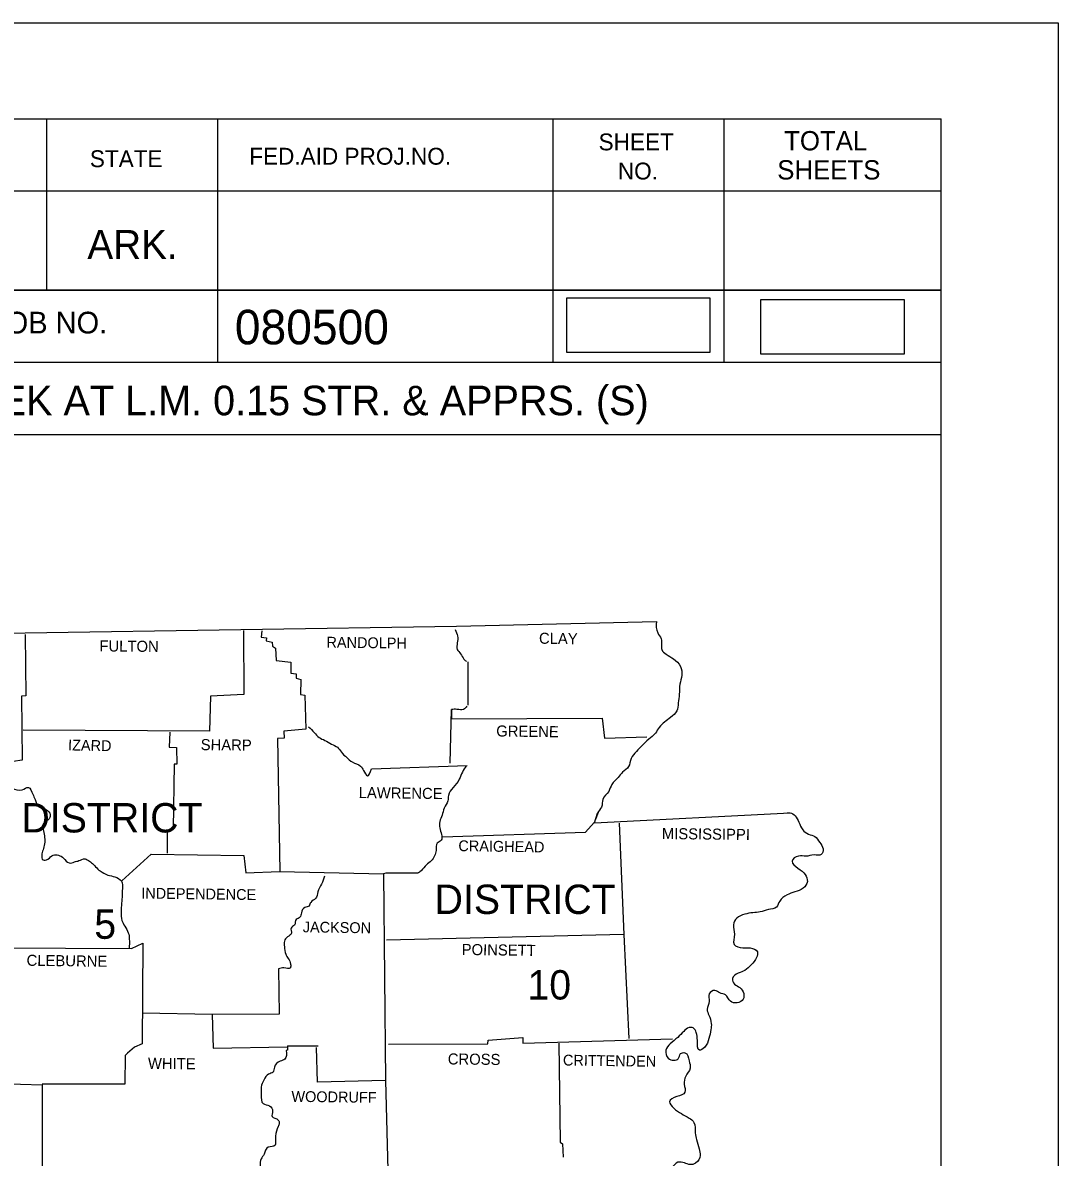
# Model space of a CAD drawing. Extents: x 1374139 to 1377472, y 1168351 to 1170484.
# Drawn here: x 1377052.4 to 1377472.1, y 1170024.3 to 1170484.1 of the extents above; entities that cross this region are included whole.
import ezdxf

# ---------------------------------------------------------------- set-up
doc = ezdxf.new("R2010")
doc.units = 0
for name, color, linetype in [('15', 7, 'Continuous'), ('26', 7, 'Continuous'), ('6', 7, 'Continuous'), ('Default', 7, 'Continuous')]:
    doc.layers.add(name, color=color, linetype=linetype)

msp = doc.modelspace()

# ---------------------------------------------------------------- linework, layer by layer
at = {"layer": '15'}
for points in [[(1377272.75, 1170350.59), (1377331.08, 1170350.59), (1377331.08, 1170372.46), (1377272.75, 1170372.46)], [(1377351.45, 1170349.9), (1377409.78, 1170349.9), (1377409.78, 1170371.76), (1377351.45, 1170371.76)]]:
    msp.add_lwpolyline(points, close=True, dxfattribs=at)
at = {"layer": '26'}
msp.add_line((1374138.81, 1170484.1), (1377472.14, 1170484.1), dxfattribs=at)
msp.add_lwpolyline([(1374138.74, 1170484.1), (1377472.14, 1170484.1), (1377472.14, 1168350.73), (1374138.74, 1168350.73)], close=True, dxfattribs=at)
at = {"layer": '6'}
for p, q in [((1374262.81, 1170445.16), (1377424.61, 1170445.16)), ((1377062.01, 1170445.16), (1377062.01, 1170375.76)), ((1377131.41, 1170445.16), (1377131.41, 1170346.36)), ((1377267.21, 1170445.16), (1377267.21, 1170346.36)), ((1377336.61, 1170445.16), (1377336.61, 1170346.36)), ((1377424.61, 1168390.56), (1377424.61, 1170445.16)), ((1377424.61, 1170415.76), (1376993.61, 1170415.76)), ((1377424.61, 1170415.96), (1377424.61, 1170415.96)), ((1377424.61, 1170375.76), (1376993.61, 1170375.76)), ((1377023.21, 1170375.76), (1377424.61, 1170375.76)), ((1377424.61, 1170346.36), (1376602.01, 1170346.36)), ((1376993.61, 1170317.16), (1377424.61, 1170317.16))]:
    msp.add_line(p, q, dxfattribs=at)
at = {"layer": 'Default'}
for p, q in [((1377284.18, 1170159.85), (1377285.43, 1170163.71)), ((1377284.49, 1170161.1), (1377285.75, 1170164.13)), ((1377159.72, 1170069.43), (1377172.15, 1170069.43))]:
    msp.add_line(p, q, dxfattribs=at)
for points in [[(1376736.44, 1170236.59), (1376905.27, 1170236.48), (1377053.43, 1170236.8), (1377228.22, 1170239.51), (1377309.24, 1170241.39)], [(1377053.43, 1170236.17), (1377053.64, 1170211.32), (1377051.86, 1170211.22), (1377052.18, 1170185.22), (1377044.87, 1170184.18), (1377045.49, 1170177.18), (1377048, 1170173.94), (1377047.79, 1170165.7), (1377033.59, 1170165.17), (1377033.07, 1170152.44), (1377020.12, 1170152.02), (1377019.5, 1170136.57), (1377020.23, 1170135.31), (1377020.54, 1170110.67), (1377042.88, 1170109.21), (1377042.57, 1170054.19), (1377060.32, 1170053.66), (1377060.32, 1169997.7), (1377046.33, 1169996.66), (1377045.29, 1169984.34), (1377021.79, 1169984.23)], [(1377141.87, 1170237.74), (1377142.08, 1170211.84), (1377128.5, 1170211.11), (1377128.08, 1170196.91), (1377052.59, 1170197.33)], [(1377149.38, 1170237.63), (1377149.07, 1170235.13), (1377151.16, 1170234.81), (1377151.06, 1170233.56), (1377153.46, 1170233.04), (1377153.67, 1170231.37), (1377154.81, 1170230.64), (1377155.13, 1170225.63), (1377161.08, 1170225), (1377161.08, 1170220.51), (1377163.27, 1170220.2), (1377163.27, 1170218.42), (1377165.15, 1170217.9), (1377165.05, 1170211.84), (1377166.72, 1170211.53), (1377167.13, 1170197.85), (1377158.26, 1170197.02), (1377158.36, 1170194.09), (1377155.65, 1170193.99), (1377156.59, 1170140.12), (1377198.67, 1170139.18), (1377199.4, 1170055.44), (1377171.94, 1170054.71), (1377171.42, 1170068.8)], [(1377232.81, 1170225.1), (1377232.81, 1170207.46)], [(1377225.71, 1170183.97), (1377226.23, 1170205.79), (1377226.23, 1170201.93), (1377287.31, 1170202.24), (1377288.15, 1170194.09), (1377305.38, 1170194.72)], [(1377112.01, 1170196.6), (1377111.8, 1170190.54), (1377114.72, 1170190.34), (1377114.82, 1170183.65), (1377113.78, 1170183.65), (1377113.36, 1170157.34), (1377110.96, 1170156.3), (1377110.96, 1170147.53)], [(1377193.76, 1170181.67), (1377232.5, 1170183.03)], [(1377284.18, 1170159.85), (1377363.43, 1170163.92)], [(1377222.58, 1170154.11), (1377280.53, 1170155.99), (1377283.97, 1170159.95)], [(1377294.2, 1170159.74), (1377295.98, 1170114.53), (1377298.07, 1170072.46)], [(1377092.58, 1170136.36), (1377104.49, 1170147.11), (1377142.08, 1170146.59), (1377142.81, 1170139.59), (1377156.48, 1170140.12)], [(1377212.35, 1170139.38), (1377199.61, 1170139.38), (1377198.67, 1170139.18)], [(1377295.98, 1170114.53), (1377199.82, 1170112.34)], [(1377042.88, 1170109.21), (1377096.55, 1170108.9), (1377101.15, 1170111.09), (1377100.83, 1170070.27), (1377097.7, 1170068.91), (1377094.88, 1170066.51), (1377093.94, 1170065.57), (1377093.84, 1170053.87), (1377060.32, 1170053.87)], [(1377156.07, 1170100.65), (1377156.28, 1170082.27), (1377129.13, 1170082.17), (1377100.93, 1170082.7)], [(1377129.13, 1170082.17), (1377129.55, 1170068.49), (1377159.72, 1170069.03)], [(1377159.72, 1170069.43), (1377159.72, 1170067.66), (1377159.2, 1170067.55)], [(1377200.65, 1170070.06), (1377240.95, 1170070.27), (1377241.06, 1170071.73), (1377255.05, 1170072.77), (1377255.05, 1170070.58), (1377315.82, 1170072.25)], [(1377269.67, 1170070.58), (1377270.19, 1170030.38), (1377271.13, 1170029.75), (1377271.44, 1170024.33)], [(1377269.67, 1170070.58), (1377270.19, 1170030.38), (1377271.13, 1170029.75), (1377271.44, 1170024.33)], [(1377269.67, 1170070.58), (1377270.19, 1170030.38), (1377271.13, 1170029.75), (1377271.44, 1170024.33)], [(1377269.67, 1170070.58), (1377270.19, 1170030.38), (1377271.13, 1170029.75), (1377271.44, 1170024.33)], [(1377269.67, 1170070.58), (1377270.19, 1170030.38), (1377271.13, 1170029.75), (1377271.44, 1170024.33)], [(1377199.4, 1170055.44), (1377200.96, 1169998.22), (1377176.11, 1169998.12), (1377176.01, 1169995.82), (1377168.81, 1169995.4), (1377168.18, 1169983.5), (1377158.28, 1169983.5)]]:
    msp.add_lwpolyline(points, dxfattribs=at)
for points in [[(1377309.24, 1170241.39), (1377309.76, 1170236.8), (1377311.22, 1170234.4), (1377311.43, 1170230.01), (1377313.21, 1170228.13), (1377316.23, 1170226.25), (1377318.95, 1170223.22), (1377319.58, 1170219.68), (1377318.74, 1170216.02), (1377318.53, 1170211.95), (1377318.11, 1170208.4), (1377317.49, 1170205.16), (1377314.98, 1170202.55), (1377312.58, 1170200.67), (1377310.39, 1170198.48), (1377308.82, 1170196.18), (1377306.11, 1170193.68), (1377303.39, 1170191.07), (1377301.2, 1170188.77), (1377299.01, 1170185.85), (1377297.96, 1170182.61), (1377295.56, 1170180.31), (1377293.68, 1170178.22), (1377291.18, 1170175.41), (1377289.92, 1170172.59), (1377287.52, 1170169.35), (1377287, 1170166.22), (1377285.43, 1170163.71), (1377285.33, 1170163.29)], [(1377227.69, 1170238.16), (1377228.63, 1170235.55), (1377228.53, 1170232.73), (1377228.53, 1170230.12), (1377229.89, 1170228.34), (1377231.24, 1170226.15), (1377232.29, 1170225.21)], [(1377232.39, 1170207.15), (1377231.03, 1170205.79), (1377228.42, 1170205.79), (1377226.23, 1170205.79)], [(1377168.28, 1170198.79), (1377170.58, 1170196.39), (1377172.56, 1170194.41), (1377174.86, 1170193.26), (1377177.58, 1170191.69), (1377179.98, 1170190.44), (1377181.54, 1170188.46), (1377183.74, 1170186.26), (1377185.93, 1170184.49), (1377189.37, 1170182.82), (1377190.52, 1170181.04), (1377192.09, 1170178.85), (1377193.76, 1170181.67)], [(1377232.18, 1170182.92), (1377230.62, 1170180.42), (1377229.36, 1170177.49), (1377226.86, 1170174.15), (1377224.98, 1170170.92), (1377224.67, 1170168.72), (1377223.2, 1170165.8), (1377222.37, 1170162.88), (1377221.43, 1170160.37), (1377221.43, 1170157.76), (1377222.16, 1170155.15), (1377221.95, 1170152.75), (1377220.38, 1170151.6), (1377219.97, 1170148.57), (1377219.34, 1170146.48), (1377217.98, 1170144.4), (1377216, 1170142.83), (1377213.91, 1170140.43), (1377212.35, 1170139.38)], [(1377048, 1170173.94), (1377052.18, 1170173.21), (1377054.68, 1170174.15), (1377056.46, 1170171.44), (1377057.4, 1170169.35), (1377058.96, 1170166.32), (1377061.47, 1170165.38), (1377063.35, 1170163.71), (1377063.35, 1170161.94), (1377061.68, 1170160.27), (1377060.43, 1170158.6), (1377060.84, 1170156.61), (1377061.26, 1170153.9), (1377061.26, 1170151.29), (1377060.63, 1170148.89), (1377060.11, 1170146.69), (1377060.63, 1170144.81), (1377062.62, 1170145.13), (1377064.71, 1170146.69), (1377066.9, 1170146.69), (1377068.99, 1170145.54), (1377071.18, 1170143.56), (1377073.37, 1170143.98), (1377075.15, 1170144.5), (1377077.65, 1170145.23), (1377079.43, 1170144.29), (1377080.99, 1170143.04), (1377082.87, 1170141.05), (1377084.65, 1170139.8), (1377086.95, 1170138.65), (1377089.77, 1170137.92), (1377092.38, 1170136.15), (1377092.79, 1170133.12), (1377092.69, 1170130.51), (1377092.48, 1170127.27), (1377092.27, 1170123.72), (1377092.58, 1170120.28), (1377093.73, 1170117.98), (1377095.19, 1170115.27), (1377095.61, 1170112.76), (1377095.51, 1170108.79)], [(1377362.28, 1170163.82), (1377363.43, 1170163.92), (1377366.98, 1170160.16), (1377368.55, 1170157.03), (1377370.84, 1170155.25), (1377373.45, 1170154.31), (1377375.44, 1170151.91), (1377376.79, 1170149.3), (1377376.06, 1170147.01), (1377373.14, 1170146.8), (1377369.9, 1170146.28), (1377366.77, 1170146.38), (1377364.26, 1170144.29), (1377366.56, 1170141.47), (1377369.59, 1170138.86), (1377370.42, 1170136.04), (1377368.75, 1170133.33), (1377365.41, 1170131.87), (1377362.18, 1170130.61), (1377359.25, 1170128.11), (1377357.9, 1170125.71), (1377354.66, 1170124.66), (1377351.32, 1170123.72), (1377348.39, 1170123.41), (1377345.05, 1170122.78), (1377341.82, 1170121.22), (1377340.46, 1170118.5), (1377340.88, 1170114.64), (1377340.77, 1170110.57), (1377344.22, 1170109.21), (1377347.25, 1170109.11), (1377350.17, 1170107.54), (1377349.86, 1170105.24), (1377347.66, 1170102.32), (1377345.05, 1170100.02), (1377342.44, 1170098.87), (1377340.04, 1170096.68), (1377340.88, 1170094.49), (1377343.07, 1170093.03), (1377344.63, 1170090.63), (1377344.43, 1170088.43), (1377341.92, 1170086.87), (1377339.21, 1170087.49), (1377337.22, 1170090.1), (1377334.92, 1170090.94), (1377332.94, 1170091.88), (1377330.64, 1170090.52), (1377330.64, 1170087.49), (1377329.81, 1170084.26), (1377330.54, 1170081.85), (1377331.48, 1170078.51), (1377331.37, 1170076.01), (1377330.54, 1170072.46), (1377328.76, 1170068.8), (1377326.68, 1170067.66), (1377325.84, 1170071.62), (1377325.42, 1170074.86), (1377324.17, 1170076.74), (1377322.5, 1170076.84), (1377320.31, 1170075.28), (1377317.91, 1170072.88), (1377314.88, 1170070.27), (1377313.1, 1170067.66), (1377314.04, 1170064.42), (1377316.34, 1170063.58), (1377318.11, 1170064.21), (1377319.05, 1170066.3), (1377320.83, 1170066.61), (1377322.5, 1170063.37)], [(1377174.76, 1170138.24), (1377173.5, 1170135), (1377172.04, 1170131.87), (1377171.1, 1170129.15), (1377169.12, 1170127.59), (1377168.49, 1170126.12), (1377166.72, 1170125.5), (1377165.36, 1170123.41), (1377164.73, 1170121.53), (1377163.27, 1170120.69), (1377162.54, 1170118.4), (1377161.18, 1170117.15), (1377161.29, 1170115.06), (1377159.72, 1170113.6), (1377158.47, 1170111.92), (1377158.47, 1170109.63), (1377158.99, 1170106.6), (1377160.03, 1170104.82), (1377160.97, 1170102.53), (1377160.87, 1170101.07), (1377158.26, 1170101.07), (1377156.07, 1170100.65)], [(1377159.2, 1170067.55), (1377158.68, 1170064.11), (1377156.69, 1170063.17), (1377154.4, 1170060.87), (1377153.87, 1170058.78), (1377152, 1170057.95), (1377150.22, 1170055.75), (1377149.07, 1170052.72), (1377149.07, 1170049.59), (1377149.8, 1170046.04), (1377152.41, 1170045.1), (1377153.67, 1170043.01), (1377153.46, 1170040.82), (1377155.96, 1170039.36), (1377156.38, 1170038.11), (1377155.96, 1170036.75), (1377154.81, 1170032.89), (1377154.92, 1170030.28), (1377154.71, 1170029.13), (1377151.89, 1170028.4), (1377150.22, 1170025.58), (1377149.07, 1170023.59), (1377148.65, 1170020.98), (1377148.97, 1170019.1), (1377148.13, 1170017.64), (1377147.82, 1170015.45), (1377146.77, 1170013.57), (1377145.83, 1170011.8), (1377146.88, 1170009.71), (1377146.57, 1170008.25), (1377145.94, 1170005.95), (1377146.46, 1170005.22)], [(1377322.5, 1170063.37), (1377322.92, 1170060.35), (1377321.14, 1170057.11), (1377320.52, 1170053.87), (1377320.83, 1170050.64), (1377317.49, 1170048.86), (1377314.56, 1170046.77), (1377316.23, 1170044.27), (1377319.37, 1170041.97), (1377322.5, 1170040.2), (1377324.48, 1170038.42), (1377325.01, 1170034.14), (1377325.53, 1170031.43), (1377326.57, 1170027.67), (1377326.99, 1170025.06), (1377325.11, 1170021.92), (1377322.92, 1170021.3), (1377320.62, 1170022.03), (1377317.91, 1170022.24), (1377315.71, 1170020.15), (1377314.15, 1170017.23), (1377312.58, 1170014.3), (1377311.43, 1170011.8), (1377310.28, 1170009.08), (1377307.99, 1170005.95), (1377305.17, 1170005.43), (1377301.83, 1170004.59), (1377299.84, 1170002.29), (1377300.16, 1169998.43), (1377302.03, 1169995.82), (1377303.5, 1169992.58), (1377304.54, 1169989.77), (1377304.02, 1169986.22), (1377302.56, 1169983.61), (1377300.68, 1169982.04), (1377299.84, 1169978.7), (1377298.48, 1169976.19), (1377297.23, 1169975.36), (1377294.73, 1169975.57), (1377292.01, 1169976.09), (1377289.71, 1169975.88), (1377287.52, 1169974.73), (1377285.33, 1169975.46), (1377283.03, 1169977.97), (1377281.15, 1169979.85), (1377279.06, 1169980.58), (1377276.87, 1169979.43), (1377276.45, 1169975.98), (1377277.5, 1169972.43), (1377278.44, 1169967.63), (1377277.5, 1169964.71), (1377277.18, 1169959.9)]]:
    msp.add_spline(points, degree=3, dxfattribs=at)

# ---------------------------------------------------------------- texts
at = {"layer": '6'}
for s, height, p in [('SHEET', 6.84, (1377285.81, 1170432.36)), ('TOTAL', 7.819, (1377361.01, 1170432.36)), ('STATE', 6.84, (1377079.61, 1170425.56)), ('FED.AID PROJ.NO.', 6.84, (1377144.21, 1170426.56)), ('NO.', 6.84, (1377293.61, 1170420.56)), ('SHEETS', 7.819, (1377358.21, 1170420.56)), ('ARK.', 11.723, (1377078.61, 1170388.36)), ('080500', 14, (1377138.37, 1170353.75)), ('JOB NO.', 8.792, (1377039.61, 1170358.16)), ('CREEK AT L.M. 0.15 STR. & APPRS. (S)', 12, (1377009.19, 1170324.99))]:
    msp.add_text(s, height=height, dxfattribs=at).set_placement(p)
at = {"layer": 'Default'}
for s, height, rotation, p in [('RANDOLPH', 4.386, 359.2584, (1377175.49, 1170230.85)), ('CLAY', 4.489, 359.2258, (1377261.63, 1170232.41)), ('FULTON', 4.489, 359.4996, (1377083.5, 1170229.28)), ('GREENE', 4.49, 359.2361, (1377244.3, 1170194.83)), ('IZARD', 4.385, 358.9259, (1377070.76, 1170189.19)), ('SHARP', 4.489, 359.3905, (1377124.53, 1170189.29)), ('LAWRENCE', 4.49, 359.2678, (1377188.54, 1170169.87)), ('MISSISSIPPI', 4.4891, 359.3097, (1377311.43, 1170153.27)), ('CRAIGHEAD', 4.386, 359.1159, (1377228.95, 1170148.36)), ('INDEPENDENCE', 4.3845, 359.2188, (1377100.42, 1170129.15)), ('JACKSON', 4.384, 359.1352, (1377165.88, 1170115.47)), ('POINSETT', 4.489, 359.1987, (1377230.3, 1170106.29)), ('CLEBURNE', 4.489, 359.2535, (1377053.95, 1170101.9)), ('WHITE', 4.49, 359.3139, (1377103.13, 1170060.14)), ('CROSS', 4.489, 359.384, (1377224.67, 1170061.91)), ('CRITTENDEN', 4.386, 359.213, (1377271.34, 1170061.49)), ('WOODRUFF', 4.384, 359.2748, (1377161.29, 1170046.77))]:
    msp.add_text(s, height=height, rotation=rotation, dxfattribs=at).set_placement(p)
for s, height, p in [('DISTRICT', 11.903, (1377051.88, 1170155.93)), ('DISTRICT', 11.903, (1377219.34, 1170122.89)), ('5', 11.9, (1377081.4, 1170112.83)), ('10', 11.903, (1377256.96, 1170088.22))]:
    msp.add_text(s, height=height, dxfattribs=at).set_placement(p)

doc.saveas('drawing.dxf')
